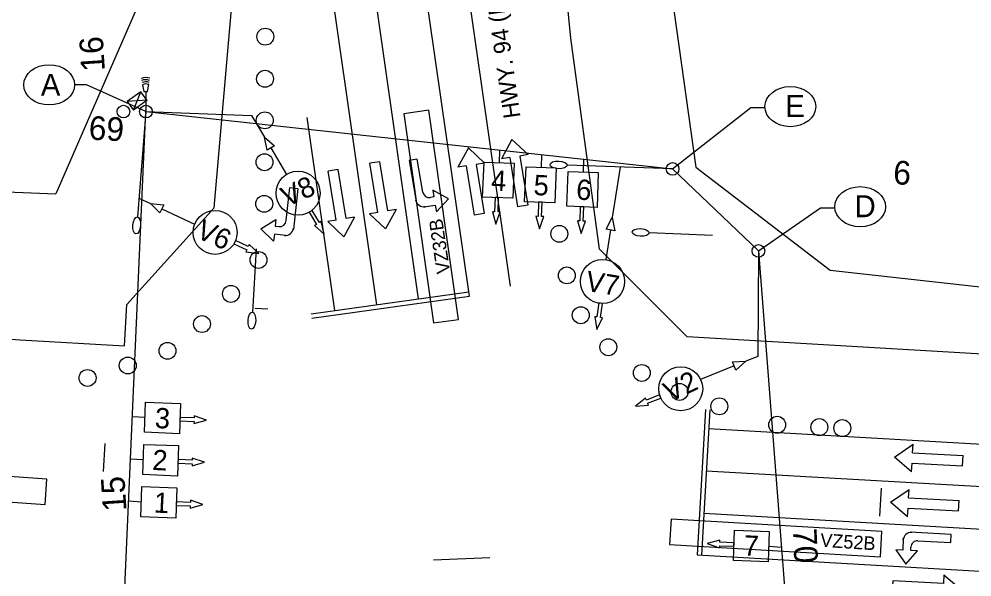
# Model space of a CAD drawing. Extents: x 0 to 1361828, y 0 to 1470398.
# Drawn here: x 686151.5 to 686377.1, y 734825.2 to 734957.2 of the extents above; entities that cross this region are included whole.
import ezdxf

# ---------------------------------------------------------------- set-up
doc = ezdxf.new("R2010")
doc.units = 0
for name, color, linetype in [('$', 7, 'Continuous'), ('BASE', 7, 'Continuous'), ('MOT Stage 1', 7, 'Continuous'), ('MOT Stage 1 Lanes', 7, 'Continuous'), ('R_Horz Alg Station', 7, 'Continuous'), ('RW-EX', 7, 'Continuous'), ('RW-PR', 7, 'Continuous'), ('SIGNAL-PLAN VIEW LABLES', 7, 'Continuous'), ('SIGNAL-PR', 7, 'Continuous'), ('SIGNAL-PR$', 7, 'Continuous'), ('Video-Zones-pr', 7, 'Continuous')]:
    doc.layers.add(name, color=color, linetype=linetype)

# ---------------------------------------------------------------- blocks, each defined once
blk = doc.blocks.new('SARROW_210')
at = {"layer": 'MOT Stage 1'}
for p, q in [((0, 0), (-6, 0)), ((0, -29.42), (0, 0)), ((-6, -29.42), (-6, 0)), ((-6, -29.42), (-11, -29.42)), ((-3, -39.81), (-11, -29.42)), ((5, -29.42), (-3, -39.81)), ((5, -29.42), (0, -29.42))]:
    blk.add_line(p, q, dxfattribs=at)
blk = doc.blocks.new('SARROW_211')
at = {"layer": 'MOT Stage 1'}
for p, q in [((0, 0), (-6, 0)), ((0, -29.42), (0, 0)), ((-6, -29.42), (-6, 0)), ((-6, -29.42), (-11, -29.42)), ((-3, -39.81), (-11, -29.42)), ((5, -29.42), (-3, -39.81)), ((5, -29.42), (0, -29.42))]:
    blk.add_line(p, q, dxfattribs=at)
blk = doc.blocks.new('SARROW_212')
at = {"layer": 'MOT Stage 1'}
for p, q in [((0, 0), (-6, 0)), ((0, -29.42), (0, 0)), ((-6, -29.42), (-6, 0)), ((-6, -29.42), (-11, -29.42)), ((-3, -39.81), (-11, -29.42)), ((5, -29.42), (-3, -39.81)), ((5, -29.42), (0, -29.42))]:
    blk.add_line(p, q, dxfattribs=at)
blk = doc.blocks.new('SARROW_221')
at = {"layer": 'MOT Stage 1'}
for p, q in [((-6, -29.42), (-6, 0)), ((0, 0), (-6, 0)), ((0, -29.42), (0, 0)), ((-6, -29.42), (-11, -29.42)), ((-3, -39.81), (-11, -29.42)), ((5, -29.42), (-3, -39.81)), ((5, -29.42), (0, -29.42))]:
    blk.add_line(p, q, dxfattribs=at)
blk = doc.blocks.new('SARROW_222')
at = {"layer": 'MOT Stage 1'}
for p, q in [((-6, -29.42), (-6, 0)), ((0, 0), (-6, 0)), ((0, -29.42), (0, 0)), ((-6, -29.42), (-11, -29.42)), ((-3, -39.81), (-11, -29.42)), ((5, -29.42), (-3, -39.81)), ((5, -29.42), (0, -29.42))]:
    blk.add_line(p, q, dxfattribs=at)
blk = doc.blocks.new('SARROW_223')
at = {"layer": 'MOT Stage 1'}
for p, q in [((-6, -29.42), (-6, 0)), ((0, 0), (-6, 0)), ((0, -29.42), (0, 0)), ((-6, -29.42), (-11, -29.42)), ((-3, -39.81), (-11, -29.42)), ((5, -29.42), (-3, -39.81)), ((5, -29.42), (0, -29.42))]:
    blk.add_line(p, q, dxfattribs=at)
blk = doc.blocks.new('SARROW_224')
at = {"layer": 'MOT Stage 1'}
for p, q in [((-6, -29.42), (-6, 0)), ((0, 0), (-6, 0)), ((0, -29.42), (0, 0)), ((-6, -29.42), (-11, -29.42)), ((-3, -39.81), (-11, -29.42)), ((5, -29.42), (-3, -39.81)), ((5, -29.42), (0, -29.42))]:
    blk.add_line(p, q, dxfattribs=at)
blk = doc.blocks.new('BAREL_1856')
at = {"layer": 'MOT Stage 1'}
blk.add_circle((0, 0.01), 2.88, dxfattribs=at)
blk = doc.blocks.new('BAREL_1857')
at = {"layer": 'MOT Stage 1'}
blk.add_circle((0, 0.01), 2.88, dxfattribs=at)
blk = doc.blocks.new('BAREL_1858')
at = {"layer": 'MOT Stage 1'}
blk.add_circle((0, 0.01), 2.88, dxfattribs=at)
blk = doc.blocks.new('BAREL_1859')
at = {"layer": 'MOT Stage 1'}
blk.add_circle((0, 0.01), 2.88, dxfattribs=at)
blk = doc.blocks.new('BAREL_1860')
at = {"layer": 'MOT Stage 1'}
blk.add_circle((0, 0.01), 2.88, dxfattribs=at)
blk = doc.blocks.new('BAREL_1861')
at = {"layer": 'MOT Stage 1'}
blk.add_circle((0, 0.01), 2.88, dxfattribs=at)
blk = doc.blocks.new('BAREL_1862')
at = {"layer": 'MOT Stage 1'}
blk.add_circle((0, 0.01), 2.88, dxfattribs=at)
blk = doc.blocks.new('BAREL_1863')
at = {"layer": 'MOT Stage 1'}
blk.add_circle((0, 0.01), 2.88, dxfattribs=at)
blk = doc.blocks.new('BAREL_1864')
at = {"layer": 'MOT Stage 1'}
blk.add_circle((0, 0.01), 2.88, dxfattribs=at)
blk = doc.blocks.new('BAREL_1865')
at = {"layer": 'MOT Stage 1'}
blk.add_circle((0, 0.01), 2.88, dxfattribs=at)
blk = doc.blocks.new('BAREL_1866')
at = {"layer": 'MOT Stage 1'}
blk.add_circle((0, 0.01), 2.88, dxfattribs=at)
blk = doc.blocks.new('BAREL_1867')
at = {"layer": 'MOT Stage 1'}
blk.add_circle((0, 0.01), 2.88, dxfattribs=at)
blk = doc.blocks.new('BAREL_1884')
at = {"layer": 'MOT Stage 1'}
blk.add_circle((0, 0.01), 2.88, dxfattribs=at)
blk = doc.blocks.new('BAREL_1885')
at = {"layer": 'MOT Stage 1'}
blk.add_circle((0, 0.01), 2.88, dxfattribs=at)
blk = doc.blocks.new('BAREL_1886')
at = {"layer": 'MOT Stage 1'}
blk.add_circle((0, 0.01), 2.88, dxfattribs=at)
blk = doc.blocks.new('BAREL_1887')
at = {"layer": 'MOT Stage 1'}
blk.add_circle((0, 0.01), 2.88, dxfattribs=at)
blk = doc.blocks.new('BAREL_1888')
at = {"layer": 'MOT Stage 1'}
blk.add_circle((0, 0.01), 2.88, dxfattribs=at)
blk = doc.blocks.new('BAREL_1889')
at = {"layer": 'MOT Stage 1'}
blk.add_circle((0, 0.01), 2.88, dxfattribs=at)
blk = doc.blocks.new('BAREL_1890')
at = {"layer": 'MOT Stage 1'}
blk.add_circle((0, 0.01), 2.88, dxfattribs=at)
blk = doc.blocks.new('BAREL_1891')
at = {"layer": 'MOT Stage 1'}
blk.add_circle((0, 0.01), 2.88, dxfattribs=at)
blk = doc.blocks.new('BAREL_1892')
at = {"layer": 'MOT Stage 1'}
blk.add_circle((0, 0.01), 2.88, dxfattribs=at)

msp = doc.modelspace()

# ---------------------------------------------------------------- linework, layer by layer
at = {"layer": '$'}
for p, q in [((686181.49, 734940.11), (686181.53, 734935.33)), ((686181.53, 734935.33), (686179.5, 734910.41)), ((686181.53, 734935.33), (686206.51, 734934.44)), ((686306.22, 734921.76), (686281.24, 734922.64)), ((686326.56, 734902.37), (686326.37, 734877.37))]:
    msp.add_line(p, q, dxfattribs=at)
for points in [[(686180.73, 734941.68), (686181.06, 734940.1), (686181.92, 734940.11), (686182.2, 734941.71)], [(686180.73, 734941.68), (686181.06, 734940.1), (686181.92, 734940.11), (686182.2, 734941.71)], [(686181.79, 734937.99), (686180.34, 734940.03), (686177.1, 734937.69), (686178.55, 734935.65)], [(686178.56, 734935.66), (686180.34, 734940.03)], [(686181.8, 734938), (686177.1, 734937.69)], [(686181.8, 734938), (686178.55, 734935.65)], [(686174.71, 734781.59), (686181.53, 734935.33)], [(686181.53, 734935.33), (686306.22, 734921.76), (686326.56, 734902.37), (686336.65, 734771.74), (686174.71, 734781.59)]]:
    msp.add_lwpolyline(points, dxfattribs=at)
for centre in [(686176.21, 734935.33), (686181.53, 734935.33), (686306.22, 734921.76), (686326.56, 734902.37)]:
    msp.add_circle(centre, 1.5, dxfattribs=at)
for radius, start, end in [(3.04, 71.4917, 110.8442), (2.54, 69.7306, 112.6053), (2.04, 67.086, 115.2499), (1.54, 62.6553, 119.6806), (1.54, 62.6553, 119.6806)]:
    msp.add_arc((686181.49, 734940.34), radius, start, end, dxfattribs=at)
for centre, major_axis in [((686279.22, 734922.72), (2.02, -0.07)), ((686179.34, 734908.39), (0.17, 2.02))]:
    msp.add_ellipse(centre, major_axis=major_axis, ratio=0.447722, dxfattribs=at)
at = {"layer": 'MOT Stage 1'}
for points in [[(686247.06, 734916.3), (686245.77, 734924.05), (686243.87, 734923.73)], [(686243.87, 734923.73), (686245.48, 734914.09), (686245.43, 734914.4)], [(686214.73, 734909.53), (686215.58, 734917.34), (686217.49, 734917.13)], [(686217.49, 734917.13), (686216.43, 734907.41), (686216.46, 734907.73)], [(686247.63, 734912.82), (686247.32, 734912.77), (686250.03, 734913.22), (686250.3, 734911.64), (686253.15, 734914.71), (686249.46, 734916.7), (686249.72, 734915.12), (686248.9, 734914.98)], [(686214.35, 734906.03), (686214.66, 734906), (686211.93, 734906.29), (686211.75, 734904.7), (686208.73, 734907.61), (686212.31, 734909.79), (686212.13, 734908.2), (686212.96, 734908.11)], [(686372.2, 734835.27), (686362.51, 734835.78), (686362.83, 734835.77)], [(686360.82, 734833.97), (686360.84, 734834.28), (686360.7, 734831.56), (686359.11, 734831.64), (686361.47, 734828.21), (686364.18, 734831.37), (686362.6, 734831.46), (686362.64, 734832.28)], [(686364.31, 734833.78), (686372.1, 734833.37), (686372.2, 734835.27)]]:
    msp.add_lwpolyline(points, dxfattribs=at)
for centre, radius, start, end in [((686247.32, 734914.72), 1.92, 189.4342, 279.4342), ((686248.64, 734916.56), 1.6, 189.4342, 279.4342), ((686213.14, 734909.7), 1.6, 263.783, 353.783), ((686214.55, 734907.94), 1.92, 263.783, 353.783), ((686362.73, 734833.87), 1.9, 86.9687, 176.9687), ((686364.23, 734832.2), 1.59, 86.9687, 176.9687)]:
    msp.add_arc(centre, radius, start, end, dxfattribs=at)
at = {"layer": 'MOT Stage 1 Lanes'}
for p, q in [((686267.87, 734894.04), (686253.16, 734996.59)), ((686246.09, 734890.99), (686231.37, 734993.54)), ((686236.18, 734889.6), (686221.47, 734992.16)), ((686226.28, 734888.22), (686219.72, 734933.95)), ((686314.76, 734860.32), (686501.05, 734849.6)), ((686314.19, 734850.33), (686500.48, 734839.61)), ((686313.61, 734840.33), (686499.9, 734829.61))]:
    msp.add_line(p, q, dxfattribs=at)
for points in [[(686220.78, 734886.44), (686258.11, 734891.66), (686243.25, 734995.2)], [(686220.65, 734887.43), (686257.97, 734892.65)], [(686314.02, 734864.85), (686312.04, 734830.43), (686499.33, 734819.65)], [(686315.02, 734864.75), (686313.04, 734830.37)]]:
    msp.add_lwpolyline(points, dxfattribs=at)
at = {"layer": 'R_Horz Alg Station'}
for points in [[(686171.81, 734856.8), (686171.43, 734850.14)], [(686355.62, 734846.22), (686355.24, 734839.56)], [(686262.94, 734829.75), (686249.62, 734829.14)]]:
    msp.add_lwpolyline(points, dxfattribs=at)
at = {"layer": 'RW-EX'}
for p, q in [((686282.11, 734952.68), (686263.01, 735155.56)), ((686197.65, 734912.58), (686202.76, 734970.41)), ((686288.94, 734902.75), (686282.11, 734952.68)), ((686177.04, 734889.69), (686197.65, 734912.58)), ((686309.65, 734882.01), (686288.94, 734902.75)), ((685894.65, 734899.71), (686151.72, 734881.33)), ((686176.47, 734879.9), (686177.04, 734889.69)), ((686151.72, 734881.33), (686176.47, 734879.9)), ((686805.63, 734853.17), (686309.65, 734882.01))]:
    msp.add_line(p, q, dxfattribs=at)
at = {"layer": 'RW-PR'}
for points in [[(686265.32, 735307.32), (686274.84, 735258.53), (686278.78, 735195.38), (686290.99, 735086.46), (686300.18, 735004.43), (686311.76, 734922.2), (686343.56, 734897.83)], [(686190.09, 735067.43), (686184.47, 735011.66), (686184.55, 734971.87), (686160.19, 734915.9)], [(685895.62, 734924.7), (685995.63, 734922.56), (686160.19, 734915.9)], [(686343.56, 734897.83), (686390.39, 734892.63), (686492.64, 734886.74), (686682.28, 734865.81), (686777.13, 734860.35), (686786.79, 734854.26)]]:
    msp.add_lwpolyline(points, dxfattribs=at)
at = {"layer": 'SIGNAL-PLAN VIEW LABLES'}
for points in [[(686181.53, 734935.33), (686167.48, 734941.68), (686164.64, 734941.68)], [(686306.22, 734921.76), (686324.75, 734936.29), (686328.11, 734936.29)], [(686206.51, 734934.44), (686209.6, 734929.29)], [(686211.1, 734926.74), (686214.81, 734920.47)], [(686265.23, 734926.22), (686265.14, 734923.22)], [(686275.2, 734925.14), (686275.1, 734922.14)], [(686285.16, 734924.05), (686285.06, 734921.05)], [(686293.79, 734922.2), (686291.95, 734910.23)], [(686179.86, 734914.83), (686182.62, 734913.54)], [(686264.19, 734914.99), (686264.08, 734911.63), (686263.58, 734911.64), (686264.41, 734908.67), (686265.43, 734911.58), (686264.92, 734911.6), (686265.03, 734914.96)], [(686264.08, 734911.63), (686263.58, 734911.64), (686264.41, 734908.67), (686265.43, 734911.58), (686264.92, 734911.6), (686265.03, 734914.96), (686264.19, 734914.99), (686264.08, 734911.63)], [(686185.3, 734912.29), (686193.06, 734908.68)], [(686274.38, 734910.53), (686273.88, 734910.55), (686274.71, 734907.57), (686275.73, 734910.49), (686275.22, 734910.5), (686275.33, 734913.86), (686274.49, 734913.89), (686274.38, 734910.53)], [(686274.49, 734913.89), (686274.38, 734910.53), (686273.88, 734910.55), (686274.71, 734907.57), (686275.73, 734910.49), (686275.22, 734910.5), (686275.33, 734913.86)], [(686284.24, 734909.45), (686283.74, 734909.47), (686284.57, 734906.49), (686285.59, 734909.41), (686285.08, 734909.42), (686285.19, 734912.78), (686284.35, 734912.81), (686284.24, 734909.45)], [(686284.35, 734912.81), (686284.24, 734909.45), (686283.74, 734909.47), (686284.57, 734906.49), (686285.59, 734909.41), (686285.08, 734909.42), (686285.19, 734912.78)], [(686326.56, 734902.37), (686341.27, 734912.58), (686344.63, 734912.58)], [(686221.88, 734908.63), (686221.45, 734908.37), (686223.76, 734906.31), (686223.03, 734909.32), (686222.6, 734909.06), (686220.87, 734911.94), (686220.15, 734911.51), (686221.88, 734908.63)], [(686220.15, 734911.51), (686221.88, 734908.63), (686221.45, 734908.37), (686223.76, 734906.31), (686223.03, 734909.32), (686222.6, 734909.06), (686220.87, 734911.94)], [(686291.5, 734907.31), (686290.41, 734900.29)], [(686205.41, 734902.64), (686205.2, 734902.18), (686208.26, 734901.77), (686205.98, 734903.86), (686205.76, 734903.4), (686202.72, 734904.82), (686202.36, 734904.05), (686205.41, 734902.64)], [(686202.36, 734904.05), (686205.41, 734902.64), (686205.2, 734902.18), (686208.26, 734901.77), (686205.98, 734903.86), (686205.76, 734903.4), (686202.72, 734904.82)], [(686288.3, 734886.72), (686287.8, 734886.79), (686288.28, 734883.74), (686289.63, 734886.52), (686289.13, 734886.6), (686289.62, 734889.92), (686288.79, 734890.04), (686288.3, 734886.72)], [(686288.79, 734890.04), (686288.3, 734886.72), (686287.8, 734886.79), (686288.28, 734883.74), (686289.63, 734886.52), (686289.13, 734886.6), (686289.62, 734889.92)], [(686207.41, 734888.82), (686210.41, 734888.64)], [(686326.37, 734877.37), (686323.55, 734876.24)], [(686320.81, 734875.13), (686312.86, 734871.95)], [(686300.01, 734867.07), (686299.82, 734867.54), (686297.43, 734865.58), (686300.51, 734865.82), (686300.32, 734866.29), (686303.44, 734867.54), (686303.13, 734868.32), (686300.01, 734867.07)], [(686303.13, 734868.32), (686300.01, 734867.07), (686299.82, 734867.54), (686297.43, 734865.58), (686300.51, 734865.82), (686300.32, 734866.29), (686303.44, 734867.54)], [(686178.33, 734863.17), (686181.32, 734863)], [(686192.92, 734862), (686192.9, 734861.5), (686195.88, 734862.33), (686192.96, 734863.34), (686192.94, 734862.84), (686189.58, 734862.95), (686189.56, 734862.11), (686192.92, 734862)], [(686189.56, 734862.11), (686192.92, 734862), (686192.9, 734861.5), (686195.88, 734862.33), (686192.96, 734863.34), (686192.94, 734862.84), (686189.58, 734862.95)], [(686177.88, 734853.18), (686180.88, 734853)], [(686192.47, 734852.01), (686192.46, 734851.51), (686195.43, 734852.34), (686192.51, 734853.35), (686192.5, 734852.85), (686189.14, 734852.96), (686189.11, 734852.12), (686192.47, 734852.01)], [(686189.11, 734852.12), (686192.47, 734852.01), (686192.46, 734851.51), (686195.43, 734852.34), (686192.51, 734853.35), (686192.5, 734852.85), (686189.14, 734852.96)], [(686177.44, 734843.19), (686180.44, 734843.01)], [(686192.03, 734842.02), (686192.01, 734841.51), (686194.99, 734842.34), (686192.07, 734843.36), (686192.06, 734842.86), (686188.7, 734842.96), (686188.67, 734842.12), (686192.03, 734842.02)], [(686188.67, 734842.12), (686192.03, 734842.02), (686192.01, 734841.51), (686194.99, 734842.34), (686192.07, 734843.36), (686192.06, 734842.86), (686188.7, 734842.96)], [(686317.4, 734833.42), (686317.41, 734833.92), (686314.43, 734833.1), (686317.35, 734832.07), (686317.37, 734832.58), (686320.72, 734832.46), (686320.75, 734833.3), (686317.4, 734833.42)], [(686320.75, 734833.3), (686317.4, 734833.42), (686317.41, 734833.92), (686314.43, 734833.1), (686317.35, 734832.07), (686317.37, 734832.58), (686320.72, 734832.46)], [(686331.98, 734832.2), (686328.99, 734832.37)]]:
    msp.add_lwpolyline(points, dxfattribs=at)
for points in [[(686209.6, 734929.29), (686212, 734927.26), (686210.2, 734926.22)], [(686261.57, 734923.34), (686268.71, 734923.1), (686268.42, 734914.84), (686261.22, 734915.09)], [(686271.53, 734922.26), (686278.67, 734922.01), (686278.38, 734913.76), (686271.18, 734914.01)], [(686281.5, 734921.18), (686288.63, 734920.93), (686288.35, 734912.67), (686281.15, 734912.92)], [(686182.62, 734913.54), (686185.75, 734913.23), (686184.85, 734911.35)], [(686291.95, 734910.23), (686292.52, 734907.14), (686290.47, 734907.47)], [(686323.55, 734876.24), (686321.19, 734874.16), (686320.43, 734876.1)], [(686181.2, 734859.43), (686181.45, 734866.56), (686189.7, 734866.28), (686189.45, 734859.08)], [(686180.76, 734849.44), (686181, 734856.57), (686189.26, 734856.28), (686189.01, 734849.08)], [(686180.31, 734839.45), (686180.56, 734846.58), (686188.82, 734846.29), (686188.57, 734839.09)], [(686320.61, 734829.12), (686320.86, 734836.25), (686329.11, 734835.97), (686328.86, 734828.77)]]:
    msp.add_lwpolyline(points, close=True, dxfattribs=at)
for centre in [(686217.55, 734916.02), (686197.9, 734906.75), (686289.64, 734895.13), (686308.14, 734869.74)]:
    msp.add_circle(centre, 5.21, dxfattribs=at)
for centre in [(686158.62, 734941.66), (686334.12, 734936.51), (686350.64, 734912.81)]:
    msp.add_ellipse(centre, major_axis=(-6.02, 0), ratio=0.790685, dxfattribs=at)
at = {"layer": 'SIGNAL-PR'}
for p, q in [((686315.68, 734905.98), (686300.69, 734906.63)), ((686207.6, 734902.86), (686206.74, 734887.88))]:
    msp.add_line(p, q, dxfattribs=at)
for centre, major_axis in [((686298.67, 734906.72), (2.02, -0.09)), ((686206.62, 734885.86), (0.12, 2.02))]:
    msp.add_ellipse(centre, major_axis=major_axis, ratio=0.447722, dxfattribs=at)
at = {"layer": 'Video-Zones-pr'}
for points in [[(686242.56, 734934.8), (686249.64, 734885.3), (686255.57, 734886.15), (686248.5, 734935.65)], [(686158.04, 734848.35), (686108.17, 734851.9), (686107.82, 734845.91), (686157.7, 734842.36)], [(686355.77, 734835.99), (686305.86, 734838.86), (686305.51, 734832.87), (686355.43, 734830)]]:
    msp.add_lwpolyline(points, close=True, dxfattribs=at)

# ---------------------------------------------------------------- block references
at = {"layer": 'MOT Stage 1'}
for name, p, xscale, yscale, rotation in [('BAREL_1856', (686209.79, 734953.06), 0.6945420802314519, 0.6945420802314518, 87.04179557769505), ('BAREL_1857', (686209.73, 734943.1), 0.6945420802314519, 0.6945420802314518, 87.04179557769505), ('BAREL_1858', (686209.67, 734933.26), 0.6945420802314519, 0.6945420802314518, 87.04179557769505), ('SARROW_222', (686271.91, 734913.2), 0.4000000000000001, -0.40000000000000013, 9.145596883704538), ('SARROW_221', (686261.62, 734911.22), 0.4000000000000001, -0.40000000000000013, 9.145596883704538), ('BAREL_1859', (686209.61, 734923.34), 0.6945420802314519, 0.6945420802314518, 87.04179557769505), ('SARROW_223', (686236.91, 734923.47), 0.4000000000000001, 0.4000000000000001, 9.14559688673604), ('SARROW_224', (686227.07, 734921.61), 0.4000000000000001, 0.4000000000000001, 9.14559688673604), ('BAREL_1860', (686209.55, 734913.5), 0.6945420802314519, 0.6945420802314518, 87.04179557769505), ('BAREL_1892', (686279.41, 734906.41), 0.6945420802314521, 0.6945420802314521, 99.12424692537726), ('BAREL_1861', (686208.18, 734900.22), 0.6945420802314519, 0.6945420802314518, 87.04179557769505), ('BAREL_1891', (686281.19, 734896.57), 0.6945420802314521, 0.6945420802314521, 99.12424692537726), ('BAREL_1862', (686201.66, 734892.19), 0.6945420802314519, 0.6945420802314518, 87.04179557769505), ('BAREL_1890', (686284.48, 734887.13), 0.6945420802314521, 0.6945420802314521, 99.12424692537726), ('BAREL_1863', (686194.81, 734885.06), 0.6945420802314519, 0.6945420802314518, 87.04179557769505), ('BAREL_1864', (686186.63, 734878.71), 0.6945420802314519, 0.6945420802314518, 87.04179557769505), ('BAREL_1889', (686291.01, 734879.56), 0.6945420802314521, 0.6945420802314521, 99.12424692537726), ('BAREL_1865', (686177.23, 734875.25), 0.6945420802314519, 0.6945420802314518, 87.04179557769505), ('BAREL_1866', (686167.71, 734872.29), 0.6945420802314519, 0.6945420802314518, 87.04179557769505), ('BAREL_1888', (686298.95, 734873.48), 0.6945420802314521, 0.6945420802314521, 99.12424692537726), ('BAREL_1887', (686307.89, 734868.99), 0.6945420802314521, 0.6945420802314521, 99.12424692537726), ('BAREL_1886', (686317.29, 734865.58), 0.6945420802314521, 0.6945420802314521, 99.12424692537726), ('BAREL_1885', (686330.99, 734861.22), 0.6945420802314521, 0.6945420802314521, 99.12424692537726), ('BAREL_1884', (686340.98, 734860.67), 0.6945420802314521, 0.6945420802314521, 99.12424692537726), ('BAREL_1867', (686346.41, 734860.44), 0.6945420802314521, 0.6945420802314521, 99.12424692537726), ('SARROW_210', (686374.9, 734851.49), 0.40758735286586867, 0.4075873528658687, -93.03128829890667), ('SARROW_211', (686373.95, 734840.82), 0.40758735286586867, 0.4075873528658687, -93.03128829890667), ('SARROW_212', (686358.38, 734824.3), 0.4075873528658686, 0.40758735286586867, 86.96871170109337)]:
    msp.add_blockref(name, p, dxfattribs=dict(at, xscale=xscale, yscale=yscale, rotation=rotation))

# ---------------------------------------------------------------- texts
at = {"layer": '$'}
for s, rotation, p in [('16', 93.7158, (686171.82, 734944.98)), ('69', 357.0415, (686167.88, 734928.72)), ('6', 357.0415, (686358.36, 734918.17)), ('15', 93.7158, (686176.94, 734840.89)), ('70', 272.6033, (686334.7, 734836.64))]:
    msp.add_text(s, height=5.6, rotation=rotation, dxfattribs=at).set_placement(p)
at = {"layer": 'BASE'}
msp.add_text('HWY. 94 (NORTH 8TH STREET)', height=4, rotation=98.1027, dxfattribs=at).set_placement((686270.23, 734934.02))
at = {"layer": 'SIGNAL-PLAN VIEW LABLES'}
for s, p in [('A', (686156.64, 734939.06)), ('E', (686332.9, 734934.04)), ('D', (686349.3, 734910.34))]:
    msp.add_text(s, height=5.2, dxfattribs=at).set_placement(p)
for s, rotation, p in [('4', 357.0414, (686263.16, 734916.7)), ('V8', 24.2898, (686214.9, 734912.68)), ('5', 357.0414, (686273.23, 734915.61)), ('6', 357.0414, (686283.31, 734914.52)), ('V6', 335.912, (686193.13, 734905.63)), ('V7', 350.436, (686285.4, 734892.97)), ('V2', 25.1497, (686305.54, 734866.48)), ('3', 357.0414, (686183.55, 734860.47)), ('2', 357.0414, (686182.96, 734850.54)), ('1', 357.0414, (686183.32, 734840.46)), ('7', 357.0414, (686322.93, 734830.3))]:
    msp.add_text(s, height=4.8, rotation=rotation, dxfattribs=at).set_placement(p)
at = {"layer": 'SIGNAL-PR$'}
for s, rotation, p in [('VZ32B', 98.422, (686253.59, 734897.22)), ('VZ52B', 356.2723, (686341.11, 734832.36))]:
    msp.add_text(s, height=3.2, rotation=rotation, dxfattribs=at).set_placement(p)

doc.saveas('drawing.dxf')
